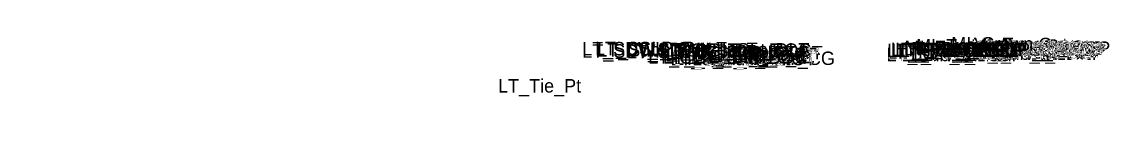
# Model space of a CAD drawing. Extents: x -26 to 4229, y -10 to 9523.
# Drawn here: x 3000 to 3161.6, y 6500 to 6510 of the extents above; entities that cross this region are included whole.
import ezdxf

# ---------------------------------------------------------------- set-up
doc = ezdxf.new("R2010")
doc.units = 0
doc.layers.add('Default', color=7, linetype='Continuous')

msp = doc.modelspace()

# ---------------------------------------------------------------- texts
at = {"layer": 'Default'}
for s, height, p in [('LT_SDWK_Out_Top', 2, (3083.24, 6507.25)), ('LT_SDWK_Out_Bot', 2, (3083.27, 6506.91)), ('LT_CSLP_Pnt', 2, (3085.17, 6507.28)), ('LT_Sub_Trench_Out_DLT', 2, (3085.49, 6507.08)), ('LT_SDWK_In_Top', 2, (3089.86, 6507.15)), ('LT_CG_Top_Face', 2, (3094.76, 6507.04)), ('LT_CG_Top_BOC', 2, (3095.28, 6507.04)), ('LT_PV2_OEEOP', 2, (3128.56, 6507)), ('LT_PV1_OEEOP', 2, (3129.12, 6507.13)), ('LT_PV2_IEEOP', 2, (3129.2, 6507)), ('LT_PV1_IEEOP', 2, (3129.77, 6507.13)), ('LT_PV2_PGL1', 2, (3130.13, 6507)), ('LT_PV2_PGL', 2, (3130.46, 6507)), ('LT_PV1_PGL', 2, (3131.03, 6507.25)), ('MI_Face In', 2, (3131.15, 6507.42)), ('MI_Bot In', 2, (3132.13, 6507.25)), ('MI_Top In', 2, (3132.86, 6507.67)), ('MI_Crown', 2, (3138.08, 6507.97)), ('RT_PV2_OEEOP', 2, (3140.02, 6507.2)), ('RT_PV3_OEEOP', 2, (3140.02, 6506.95)), ('RT_PV1_OEEOP', 2, (3140.59, 6507.33)), ('RT_PV2_IEEOP', 2, (3140.66, 6507.2)), ('MI_Face Out', 2, (3141.02, 6507.62)), ('MI_Top Out', 2, (3141.23, 6507.87)), ('RT_PV1_IEEOP', 2, (3141.23, 6507.33)), ('RT_PV2_PGL1', 2, (3141.59, 6507.2)), ('RT_PV3_PGL1', 2, (3141.59, 6506.95)), ('RT_PV2_PGL', 2, (3141.92, 6507.2)), ('MI_Bot Out', 2, (3142.02, 6507.45)), ('RT_PV1_PGL', 2, (3142.49, 6507.45)), ('LT_SDWK_In_Bot', 2, (3089.89, 6506.81)), ('LT_CG1_Shelf_Out', 2, (3093.05, 6506.01)), ('LT_CG_Bot_BOC', 2, (3095.31, 6506.02)), ('LT_CG_Top_Gut', 2, (3095.74, 6506.54)), ('LT_Sub_OEOP', 2, (3096.36, 6505.76)), ('LT_Sub_OEOT_CG', 2, (3096.87, 6505.82)), ('LT_CG_Bot_IE', 2, (3099.41, 6506.07)), ('LT_Sub_OEOT', 2, (3099.58, 6505.78)), ('LT_PV2_OEOT', 2, (3099.67, 6506.41)), ('LT_PV3_OEOT', 2, (3099.67, 6506.16)), ('LT_PV1_OEOT', 2, (3100.24, 6506.66)), ('LT_Sub_OEEOP', 2, (3128.46, 6506.38)), ('LT_PV3_OEEOP', 2, (3128.56, 6506.75)), ('LT_PV3_PGL1', 2, (3130.13, 6506.75)), ('LT_PV4_PGL', 2, (3130.46, 6506.38)), ('RT_Sub_OEEOP', 2, (3139.92, 6506.58)), ('RT_PV4_PGL', 2, (3141.92, 6506.58)), ('LT_Tie_Pt', 2, (3070.76, 6501.72)), ('-', 0.0001, (3000, 6500)), ('-', 0.0001, (3000, 6500)), ('-', 0.0001, (3000, 6500)), ('-', 0.0001, (3000, 6500)), ('-', 0.0001, (3000, 6500)), ('-', 0.0001, (3000, 6500)), ('-', 0.0001, (3000, 6500))]:
    msp.add_text(s, height=height, dxfattribs=at).set_placement(p)

doc.saveas('drawing.dxf')
